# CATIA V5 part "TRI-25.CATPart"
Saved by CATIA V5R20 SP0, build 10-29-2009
Part number: _TRI-25
Definition: NONE
Nomenclature: _TRI-25
Source: Unknown
Description: PART-_TRI-25-DESC
Bounding box of the stored display mesh (mm): x 0 to 22.5, y -12.5 to 12.5, z -12.5 to 12.5
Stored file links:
  C:\Users\Utente\Desktop\IO LAVORO\3D X SITO CF\X SITO\PLASTICA\TRI\TRI-25.CATPart
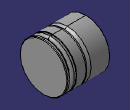
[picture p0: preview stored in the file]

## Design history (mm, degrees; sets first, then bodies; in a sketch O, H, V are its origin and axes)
Body1 "_TRI-25" (main body)
  Solid1: solid without history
